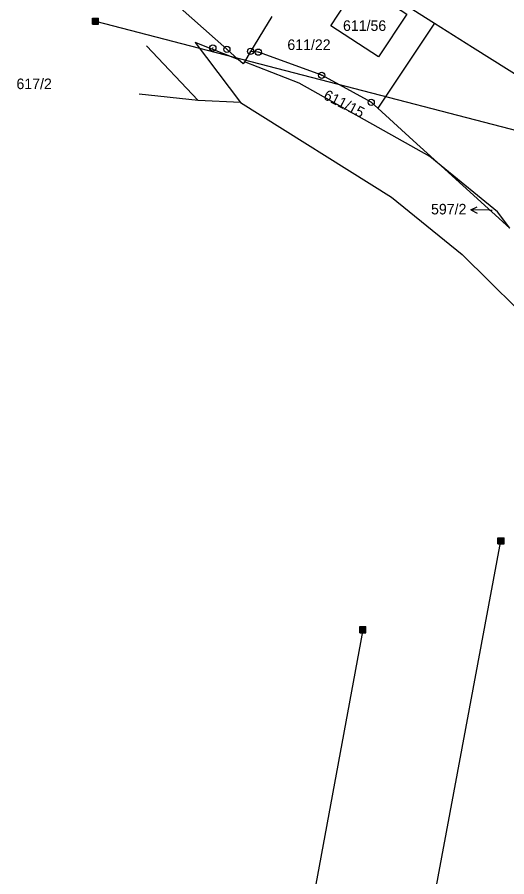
# Model space of a CAD drawing. Extents: x -776701 to -776081, y -974398 to -973771.
# Drawn here: x -776699.1 to -776620.3, y -974047.3 to -973908.9 of the extents above; entities that cross this region are included whole.
import ezdxf

# ---------------------------------------------------------------- set-up
doc = ezdxf.new("R2010")
doc.units = 0
for name, color, linetype in [('Hranice parcel', 7, 'Continuous'), ('Parcelní čísla', 7, 'Continuous'), ('Pop  PČ popisy', 7, 'Continuous'), ('Poz předměty', 7, 'Continuous'), ('Značky bodu BP', 7, 'Continuous')]:
    doc.layers.add(name, color=color, linetype=linetype)

msp = doc.modelspace()

# ---------------------------------------------------------------- linework, layer by layer
at = {"layer": 'Hranice parcel'}
for p, q in [((-776697.06, -973885.88), (-776665.35, -973914.08)), ((-776651.24, -973897.61), (-776631.93, -973909.89)), ((-776658.09, -973908.78), (-776661.54, -973914.42)), ((-776631.93, -973909.89), (-776641.05, -973923.57)), ((-776678.3, -973913.51), (-776669.96, -973922.31)), ((-776663.51, -973915.71), (-776670.45, -973912.99)), ((-776670.45, -973912.99), (-776663.13, -973922.66)), ((-776663.51, -973915.71), (-776665.35, -973914.08)), ((-776661.54, -973914.42), (-776662.53, -973916.09)), ((-776669.96, -973922.31), (-776679.48, -973921.31)), ((-776663.13, -973922.66), (-776669.96, -973922.31)), ((-776619.82, -973942.86), (-776630.86, -973932.83))]:
    msp.add_line(p, q, dxfattribs=at)
for points in [[(-776644.12, -973903.4), (-776636.4, -973908.42), (-776640.94, -973915.31), (-776648.62, -973910.3), (-776644.12, -973903.4)], [(-776631.93, -973909.89), (-776625.84, -973913.71), (-776598.02, -973931.18)], [(-776641.05, -973923.57), (-776642.12, -973922.6), (-776650.09, -973918.26), (-776660.28, -973914.54), (-776661.54, -973914.42)], [(-776662.53, -973916.09), (-776662.72, -973916.41), (-776663.51, -973915.71)], [(-776630.86, -973932.83), (-776632.69, -973931.33), (-776653.72, -973919.55), (-776662.53, -973916.09)], [(-776663.13, -973922.66), (-776638.85, -973937.91), (-776627.48, -973947.13), (-776614.36, -973960.12), (-776586.99, -973987.85), (-776556.98, -974024.6), (-776534.64, -974053.84), (-776493.63, -974104.03)], [(-776641.05, -973923.57), (-776635.36, -973928.74), (-776630.86, -973932.83)], [(-776619.82, -973942.86), (-776621.79, -973940.26), (-776630.86, -973932.83)]]:
    msp.add_lwpolyline(points, dxfattribs=at)
at = {"layer": 'Pop  PČ popisy'}
for p, q in [((-776626.07, -973939.94), (-776625.06, -973939.45)), ((-776623.07, -973939.99), (-776626.07, -973939.94)), ((-776626.07, -973939.94), (-776625.08, -973940.46)), ((-776623.07, -973939.99), (-776622.63, -973939.99))]:
    msp.add_line(p, q, dxfattribs=at)
at = {"layer": 'Poz předměty'}
for p, q in [((-776686.99, -973909.04), (-776685.99, -973909.04)), ((-776686.99, -973910.04), (-776686.99, -973909.04)), ((-776686.99, -973909.24), (-776685.99, -973909.24)), ((-776686.99, -973909.44), (-776685.99, -973909.44)), ((-776686.99, -973909.64), (-776685.99, -973909.64)), ((-776686.79, -973910.04), (-776686.79, -973909.04)), ((-776686.59, -973910.04), (-776686.59, -973909.04)), ((-776686.49, -973909.54), (-776575.4, -973938.41)), ((-776686.39, -973910.04), (-776686.39, -973909.04)), ((-776686.19, -973910.04), (-776686.19, -973909.04)), ((-776685.99, -973910.04), (-776685.99, -973909.04)), ((-776686.99, -973909.84), (-776685.99, -973909.84)), ((-776686.99, -973910.04), (-776685.99, -973910.04)), ((-776621.74, -973992.72), (-776620.74, -973992.72)), ((-776621.74, -973993.72), (-776621.74, -973992.72)), ((-776621.54, -973993.72), (-776621.54, -973992.72)), ((-776621.34, -973993.72), (-776621.34, -973992.72)), ((-776621.14, -973993.72), (-776621.14, -973992.72)), ((-776620.94, -973993.72), (-776620.94, -973992.72)), ((-776620.74, -973993.72), (-776620.74, -973992.72)), ((-776668.16, -974244.33), (-776621.24, -973993.22)), ((-776621.74, -973992.92), (-776620.74, -973992.92)), ((-776621.74, -973993.12), (-776620.74, -973993.12)), ((-776621.74, -973993.32), (-776620.74, -973993.32)), ((-776621.74, -973993.52), (-776620.74, -973993.52)), ((-776621.74, -973993.72), (-776620.74, -973993.72)), ((-776643.47, -974007.53), (-776683.78, -974225.34)), ((-776643.97, -974007.03), (-776642.97, -974007.03)), ((-776643.97, -974008.03), (-776643.97, -974007.03)), ((-776643.97, -974007.23), (-776642.97, -974007.23)), ((-776643.97, -974007.43), (-776642.97, -974007.43)), ((-776643.97, -974007.63), (-776642.97, -974007.63)), ((-776643.97, -974007.83), (-776642.97, -974007.83)), ((-776643.77, -974008.03), (-776643.77, -974007.03)), ((-776643.57, -974008.03), (-776643.57, -974007.03)), ((-776643.37, -974008.03), (-776643.37, -974007.03)), ((-776643.17, -974008.03), (-776643.17, -974007.03)), ((-776642.97, -974008.03), (-776642.97, -974007.03)), ((-776643.97, -974008.03), (-776642.97, -974008.03))]:
    msp.add_line(p, q, dxfattribs=at)
at = {"layer": 'Značky bodu BP'}
for centre, radius in [((-776667.61, -973913.87), 0.5), ((-776667.61, -973913.87), 0.0303), ((-776665.35, -973914.08), 0.5), ((-776665.35, -973914.08), 0.0303), ((-776661.54, -973914.42), 0.5), ((-776661.54, -973914.42), 0.0303), ((-776660.28, -973914.54), 0.5), ((-776660.28, -973914.54), 0.0303), ((-776650.09, -973918.26), 0.5), ((-776650.09, -973918.26), 0.0303), ((-776642.12, -973922.6), 0.5), ((-776642.12, -973922.6), 0.0303)]:
    msp.add_circle(centre, radius, dxfattribs=at)

# ---------------------------------------------------------------- texts
at = {"layer": 'Parcelní čísla'}
for s, p in [('611/56', (-776646.66, -973911.12)), ('611/22', (-776655.61, -973914.19)), ('617/2', (-776699.21, -973920.49)), ('597/2', (-776632.49, -973940.66))]:
    msp.add_text(s, height=1.7, dxfattribs=at).set_placement(p)
msp.add_text('611/15', height=1.7, rotation=333, dxfattribs=at).set_placement((-776649.95, -973922.01))

doc.saveas('drawing.dxf')
